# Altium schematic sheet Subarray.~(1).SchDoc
size A3; SheetNumber: 2; SheetTotal: 6; PageSetup: Record=PageOptions¦CenterHorizontal=True¦CenterVertical=True¦PrintScale=1.01¦XCorrection=1.00¦YCorrection=1.00¦PrintKind=1¦BorderSize=5000000¦LeftOffset=0¦BottomOffset=0¦Orientation=2¦PaperLength=1000¦PaperWidth=1000¦Scale=100¦PaperSource=7¦PrintQuality=600¦MediaType=1¦DitherType=10¦PaperKind=A3¦PrintScaleMode=1
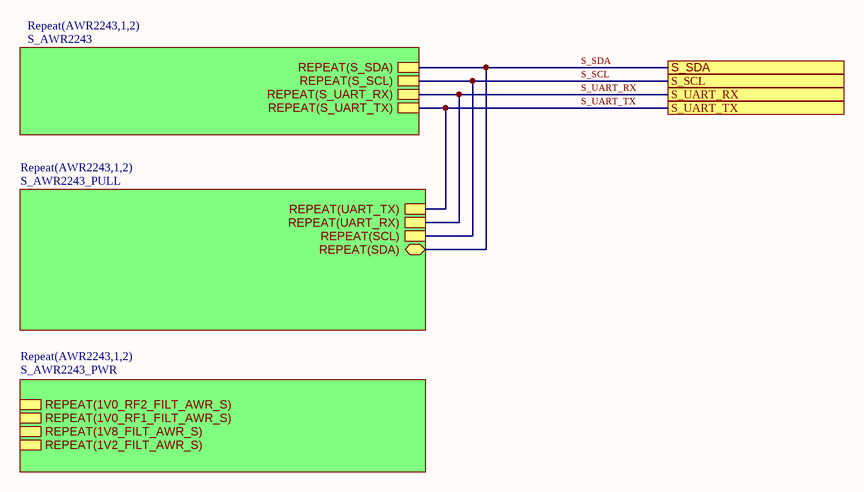
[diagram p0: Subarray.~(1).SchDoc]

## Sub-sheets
Repeat(AWR2243,1,2) = S_AWR2243: REPEAT(S_SCL), REPEAT(S_SDA), REPEAT(S_UART_RX), REPEAT(S_UART_TX)
Repeat(AWR2243,1,2) = S_AWR2243_PWR: REPEAT(1V2_FILT_AWR_S), REPEAT(1V8_FILT_AWR_S), REPEAT(1V0_RF1_FILT_AWR_S), REPEAT(1V0_RF2_FILT_AWR_S)
Repeat(AWR2243,1,2) = S_AWR2243_PULL: REPEAT(SCL), REPEAT(SDA) (bidir), REPEAT(UART_RX), REPEAT(UART_TX)

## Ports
S_SCL, S_SDA, S_UART_RX, S_UART_TX

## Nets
S_SCL: port S_SCL, sheet Repeat(AWR2243,1,2)/REPEAT(S_SCL), sheet Repeat(AWR2243,1,2)/REPEAT(SCL)
S_SDA: port S_SDA, sheet Repeat(AWR2243,1,2)/REPEAT(S_SDA), sheet Repeat(AWR2243,1,2)/REPEAT(SDA)
S_UART_RX: port S_UART_RX, sheet Repeat(AWR2243,1,2)/REPEAT(S_UART_RX), sheet Repeat(AWR2243,1,2)/REPEAT(UART_RX)
S_UART_TX: port S_UART_TX, sheet Repeat(AWR2243,1,2)/REPEAT(S_UART_TX), sheet Repeat(AWR2243,1,2)/REPEAT(UART_TX)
